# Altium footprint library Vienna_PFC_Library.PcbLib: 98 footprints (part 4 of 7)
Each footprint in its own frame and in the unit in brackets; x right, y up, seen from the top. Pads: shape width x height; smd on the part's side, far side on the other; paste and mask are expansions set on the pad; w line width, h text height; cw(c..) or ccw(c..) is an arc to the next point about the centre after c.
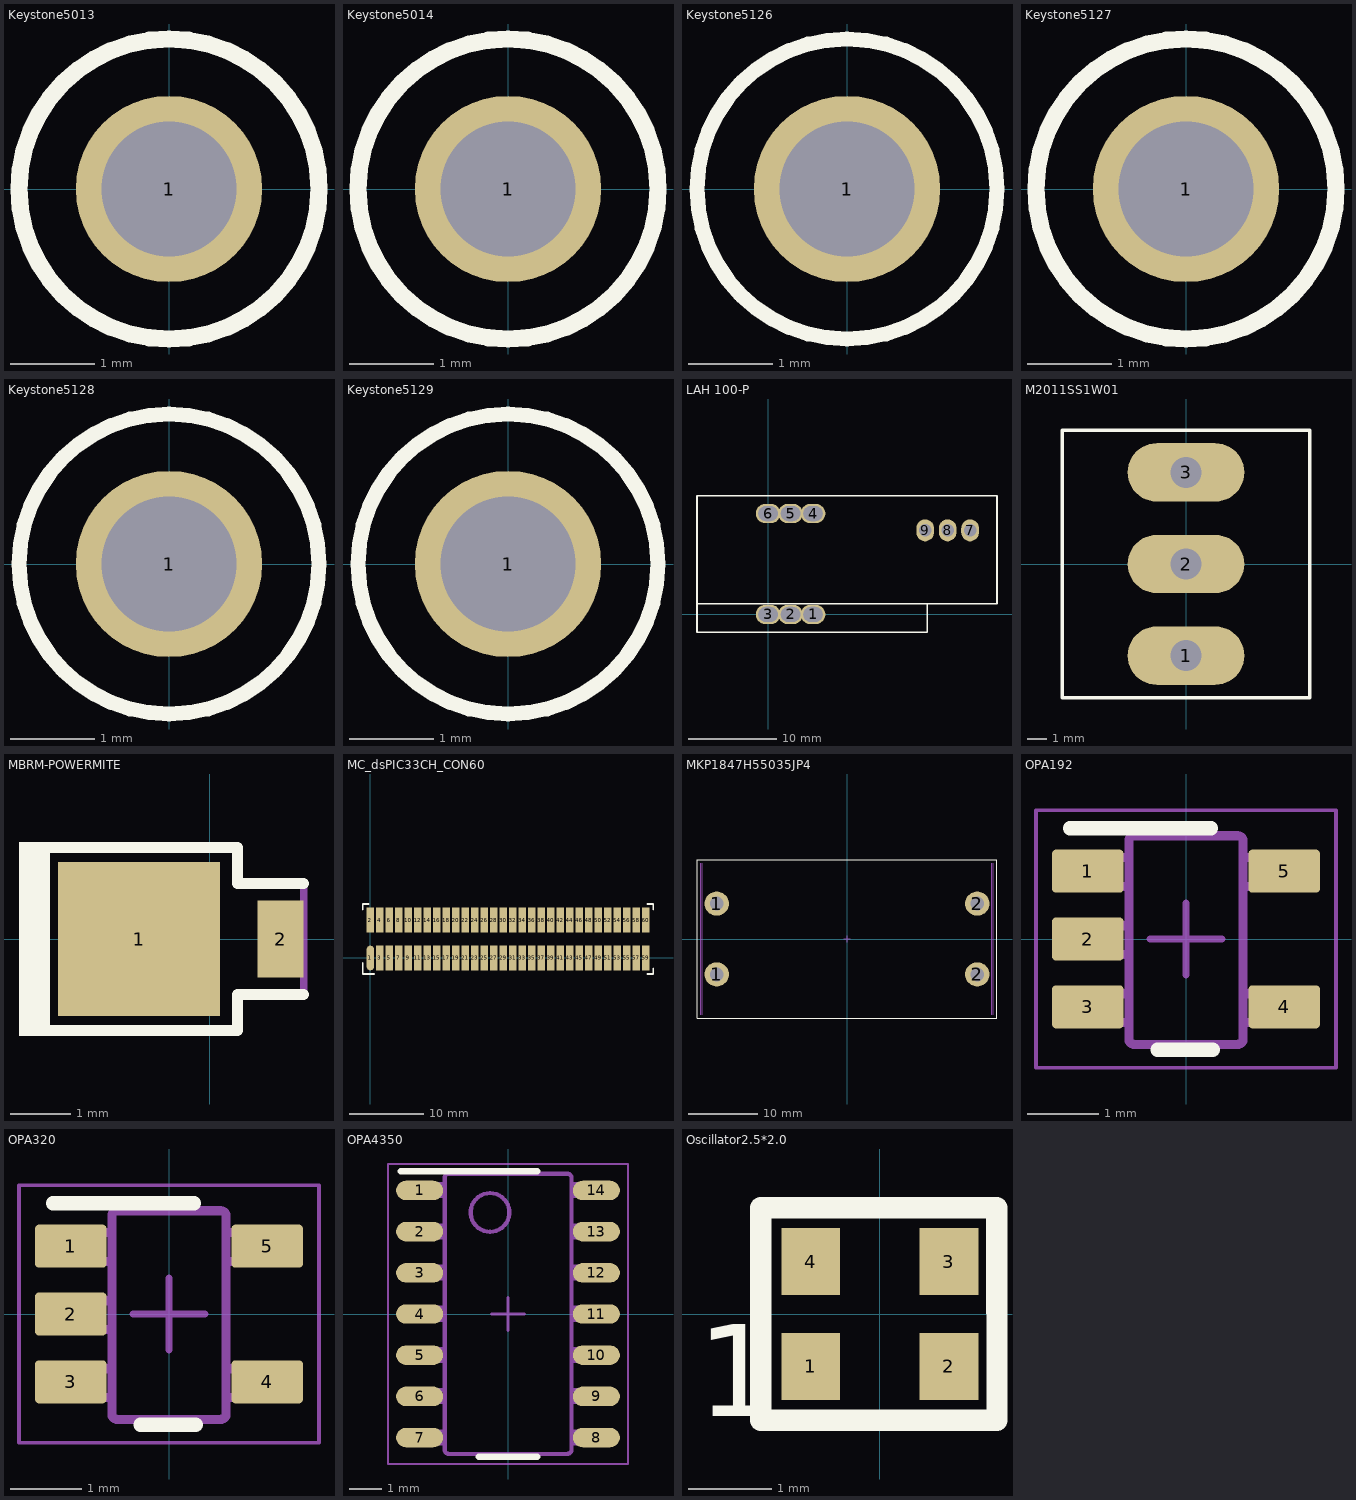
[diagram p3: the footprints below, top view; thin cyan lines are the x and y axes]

## Keystone5013 [mil] "Keystone Multipurpose loops"
height 320
pads (1):
  round 87 hole 63: 1(0,0)
Top Overlay:
  circle w7.99: c0,0 r70
Mechanical 5:
  circle w5: c0,0 r69.46
3D body "Keystone_5013.stp": height 318.9, standoff -125.98, extent -63,-63.5 62.74,62.49

## Keystone5014 [mil] "Keystone Multipurpose loops"
height 320
pads (1):
  round 87 hole 63: 1(0,0)
Top Overlay:
  circle w7.99: c0,0 r70
Mechanical 5:
  circle w5: c0,0 r69.46
3D body "Keystone_5014.stp": height 318.9, standoff -125.98, extent -63,-63.5 62.74,62.49

## Keystone5126 [mil] "Keystone Multipurpose loops"
height 320
pads (1):
  round 87 hole 63: 1(0,0)
Top Overlay:
  circle w7: c0,0 r70
Mechanical 5:
  circle w5: c0,0 r69.46
3D body "Keystone_5126.stp": height 318.9, standoff -125.98, extent -63.12,-63.37 62.86,62.36

## Keystone5127 [mil] "Keystone Multipurpose loops"
height 320
pads (1):
  round 87 hole 63: 1(0,0)
Top Overlay:
  circle w7.99: c0,0 r70
Mechanical 5:
  circle w5: c0,0 r69.46
3D body "Keystone_5127.stp": height 318.9, standoff -125.98, extent -63,-63.5 62.74,62.49

## Keystone5128 [mil] "Keystone Multipurpose loops"
height 320
pads (1):
  round 87 hole 63: 1(0,0)
Top Overlay:
  circle w7: c0,0 r70
Mechanical 5:
  circle w5: c0,0 r69.46
3D body "Keystone_5128.stp": height 318.9, standoff -125.98, extent -63.12,-63.37 62.86,62.36

## Keystone5129 [mil] "Keystone Multipurpose loops"
height 320
pads (1):
  round 87 hole 63: 1(0,0)
Top Overlay:
  circle w7: c0,0 r70
Mechanical 5:
  circle w5: c0,0 r69.46
3D body "Keystone_5129.stp": height 318.9, standoff -125.98, extent -63.12,-63.37 62.86,62.36

## LAH 100-P [mm] "Inductor"
height 24
pads (9):
  oval 2.8x2.2 hole 1.7 slot 2.2 at 0 deg: 1(5.08,0) 2(2.54,0) 3(0,0) 4(5.08,11.43) 5(2.54,11.43) 6(0,11.43)
  oval 2x2.5 hole 1.4: 7(22.86,9.525) 8(20.32,9.525) 9(17.78,9.525)
Top Overlay:
  lines w0.178: -7.964,1.23 25.908,1.23 ; 18.034,1.23 18.034,-2.032 -8.052,-2.032 -8.052,13.462 25.908,13.462 25.908,1.27
3D body "LAH 100-P_blackbox.stp": height 21.05, standoff -4.9, extent -7.76,-1.731 25.54,13.208

## M2011SS1W01 [mm] "Capacitor"
height 34
pads (3):
  oval 6x3 hole 1.6 square: 1(0,-4.7) 2(0,0) 3(0,4.7)
Top Overlay:
  lines w0.178: -6.35,-6.858 -6.35,6.858 6.35,6.858 6.35,-6.858 -6.35,-6.858
Mechanical 15:
  lines w0.1: -0.5,0 0.5,0 ; 0,-0.5 0,0.5
3D body "M2011SS1W01.stp": height 28.88, standoff -4.67, extent -6.019,-6.509 5.97,6.495

## MBRM-POWERMITE [mil] "On Semi recommended land pattern, 457-04.pdf Rev 04E dated 2008-11-26"
height 45.28
pads (2):
  rect 105x100 smd: 1(-46,0)
  rect 30x50 smd: 2(46,0)
Top Overlay:
  rectangle: -124,-63 -104,63
  lines w7: -109.7,-59.5 -19,-59.5 18,-59.5 18,-36 61,-36 ; -109.7,59.5 -19,59.5 18,59.5 18,36 61,36
Mechanical 5:
  rectangle: -124,-63 -104,63
  lines w5: -109.7,-59.5 -19,-59.5 18,-59.5 18,-36 61,-36 61,36 18,36 18,59.5 -19,59.5 -109.7,59.5
3D body "PowerMite.stp": height 45.31, standoff 0, extent -94.48,-40.35 59.06,40.36

## MC_Connector [mm] "Microchip dsPIC33CH Connector"

## MC_dsPIC33CH_CON60 [mil]
pads (60):
  oval 40x130 smd: 1(0,0)
  rect 40x130 smd: 2(0,200) 3(50,0) 4(50,200) 5(100,0) 6(100,200) 7(150,0) 8(150,200) 9(200,0) 10(200,200) 11(250,0) 12(250,200) 13(300,0) 14(300,200) 15(350,0) 16(350,200) 17(400,0) 18(400,200) 19(450,0) 20(450,200) 21(500,0) 22(500,200) 23(550,0) 24(550,200) 25(600,0) 26(600,200) 27(650,0) 28(650,200) 29(700,0) 30(700,200) 31(750,0) 32(750,200) 33(800,0) 34(800,200) 35(850,0) 36(850,200) 37(900,0) 38(900,200) 39(950,0) 40(950,200) 41(1000,0) 42(1000,200) 43(1050,0) 44(1050,200) 45(1100,0) 46(1100,200) 47(1150,0) 48(1150,200) 49(1200,0) 50(1200,200) 51(1250,0) 52(1250,200) 53(1300,0) 54(1300,200) 55(1350,0) 56(1350,200) 57(1400,0) 58(1400,200) 59(1450,0) 60(1450,200)
Top Overlay:
  lines w10: -40,-25 -40,-85 20,-85 ; -40,255 -40,285 -10,285 ; 1460,-85 1490,-85 1490,-55 ; 1460,285 1490,285 1490,255

## MKP1847H55035JP4 [mm] "Capacitor"
height 38.5
pads (4):
  round 3.5 hole 2: 1(-18.75,-5.1) 1(-18.75,5.1) 2(18.75,-5.1) 2(18.75,5.1)
Top Overlay:
  lines w0.178: -21.59,-11.43 -21.59,11.43 21.59,11.43 21.59,-11.43 -21.59,-11.43
Mechanical 13:
  lines w0.1: -21.082,-10.922 -21.082,10.922 ; -20.828,-10.922 -20.828,10.922 ; 20.828,-10.922 20.828,10.922 ; 21.082,-10.922 21.082,10.922
Mechanical 15:
  lines w0.1: -0.5,0 0.5,0 ; 0,-0.5 0,0.5
3D body: height 2.8, standoff 0, extent 20.794,-10.922 21.082,10.922
3D body: height 2.8, standoff 0, extent 20.828,-4.318 21.082,4.318
3D body: height 2.8, standoff 0, extent -21.082,-4.318 -20.828,4.318
3D body "MKP1847H55035+P4.step": height 39, standoff -6, extent -21.35,-11.1 21.35,11.1
3D body: height 2.8, standoff 0, extent -21.116,-10.922 -20.828,10.922

## OPA192 [mm] "SOT23, 5-Leads, Body 2.9x1.6mm, Pitch 0.95mm, Lead Span 2.8mm, IPC Medium Density"
height 1.45
pads (5):
  rrect17% 1x0.6 smd: 1(-1.375,0.95) 2(-1.375,0) 3(-1.375,-0.95) 4(1.375,-0.95) 5(1.375,0.95)
Top Overlay:
  lines w0.2: -1.625,1.55 0.35,1.55 ; -0.4,-1.55 0.375,-1.55
Mechanical 5:
  lines w0.127: -0.801,1.371 cw(c-0.725,1.37) -0.725,1.446 ; -0.801,1.37 -0.801,-1.399 -0.801,-1.4 ccw(c-0.725,-1.399) -0.725,-1.475 ; -0.801,1.37 -0.801,1.371 ; -0.725,-1.475 -0.725,-1.475 ; -0.725,-1.475 0.723,-1.475 0.724,-1.475 ccw(c0.723,-1.399) 0.799,-1.4 0.799,-1.399 0.799,1.37 ; -0.725,1.446 0.723,1.446 0.724,1.446 cw(c0.723,1.37) 0.799,1.371 ; -0.725,1.446 -0.725,1.446 ; 0.799,1.37 0.799,1.371 ; -1.423,-1.167 -1.199,-1.167 -1.105,-1.167 -1.088,-1.167 -0.835,-1.167 -0.801,-1.167 -0.801,-0.767 -0.835,-0.767 -1.088,-0.767 -1.105,-0.767 -1.199,-0.767 -1.423,-0.767 -1.423,-1.167 ; -1.423,-0.215 -1.199,-0.215 -1.105,-0.215 -1.088,-0.215 -0.835,-0.215 -0.801,-0.215 -0.801,0.186 -0.835,0.186 -1.088,0.186 -1.105,0.186 -1.199,0.186 -1.423,0.186 -1.423,-0.215 ; -1.423,0.738 -1.199,0.738 -1.105,0.738 -1.088,0.738 -0.835,0.738 -0.801,0.738 -0.801,1.138 -0.835,1.138 -1.088,1.138 -1.105,1.138 -1.199,1.138 -1.423,1.138 -1.423,0.738 ; 0.799,-1.167 0.799,-0.767 0.834,-0.767 1.087,-0.767 1.103,-0.767 1.198,-0.767 1.422,-0.767 1.422,-1.167 1.198,-1.167 1.103,-1.167 1.087,-1.167 0.834,-1.167 0.799,-1.167 ; 0.799,0.738 0.799,1.138 0.834,1.138 1.087,1.138 1.103,1.138 1.198,1.138 1.422,1.138 1.422,0.738 1.198,0.738 1.103,0.738 1.087,0.738 0.834,0.738 0.799,0.738
Mechanical 15:
  lines w0.05: -2.1,-1.8 2.1,-1.8 2.1,1.8 -2.1,1.8 -2.1,-1.8
  lines w0.1: -0.5,0 0.5,0 ; 0,-0.5 0,0.5
3D body "DBV0005A.stp": height 1.09, standoff 0, extent -1.422,-1.46 1.422,1.461

## OPA320 [mm] "SOT23, 5-Leads, Body 2.9x1.6mm, Pitch 0.95mm, Lead Span 2.8mm, IPC Medium Density"
height 1.45
pads (5):
  rrect17% 1x0.6 smd: 1(-1.375,0.95) 2(-1.375,0) 3(-1.375,-0.95) 4(1.375,-0.95) 5(1.375,0.95)
Top Overlay:
  lines w0.2: -1.625,1.55 0.35,1.55 ; -0.4,-1.55 0.375,-1.55
Mechanical 5:
  lines w0.127: -0.801,1.371 cw(c-0.725,1.37) -0.725,1.446 ; -0.801,1.37 -0.801,1.371 ; -0.801,1.37 -0.801,-1.399 -0.801,-1.4 ccw(c-0.725,-1.399) -0.725,-1.475 ; -0.725,-1.475 0.723,-1.475 0.724,-1.475 ccw(c0.723,-1.399) 0.799,-1.4 0.799,-1.399 0.799,1.37 ; -0.725,-1.475 -0.725,-1.475 ; -0.725,1.446 -0.725,1.446 ; -0.725,1.446 0.723,1.446 0.724,1.446 cw(c0.723,1.37) 0.799,1.371 ; 0.799,1.37 0.799,1.371 ; -1.423,-1.167 -1.423,-0.767 -1.199,-0.767 -1.105,-0.767 -1.088,-0.767 -0.835,-0.767 -0.801,-0.767 -0.801,-1.167 -0.835,-1.167 -1.088,-1.167 -1.105,-1.167 -1.199,-1.167 -1.423,-1.167 ; -1.423,-0.215 -1.423,0.186 -1.199,0.186 -1.105,0.186 -1.088,0.186 -0.835,0.186 -0.801,0.186 -0.801,-0.215 -0.835,-0.215 -1.088,-0.215 -1.105,-0.215 -1.199,-0.215 -1.423,-0.215 ; -1.423,0.738 -1.423,1.138 -1.199,1.138 -1.105,1.138 -1.088,1.138 -0.835,1.138 -0.801,1.138 -0.801,0.738 -0.835,0.738 -1.088,0.738 -1.105,0.738 -1.199,0.738 -1.423,0.738 ; 0.799,-1.167 0.834,-1.167 1.087,-1.167 1.103,-1.167 1.198,-1.167 1.422,-1.167 1.422,-0.767 1.198,-0.767 1.103,-0.767 1.087,-0.767 0.834,-0.767 0.799,-0.767 0.799,-1.167 ; 0.799,0.738 0.834,0.738 1.087,0.738 1.103,0.738 1.198,0.738 1.422,0.738 1.422,1.138 1.198,1.138 1.103,1.138 1.087,1.138 0.834,1.138 0.799,1.138 0.799,0.738
Mechanical 15:
  lines w0.05: -2.1,-1.8 -2.1,1.8 2.1,1.8 2.1,-1.8 -2.1,-1.8
  lines w0.1: -0.5,0 0.5,0 ; 0,-0.5 0,0.5
3D body "DBV0005A.stp": height 1.09, standoff 0, extent -1.422,-1.46 1.422,1.461

## OPA4350 [mm] "SOIC, 14-Leads, Body 8.7x3.9mm, Pitch 1.27mm, IPC Medium Density"
height 1.75
pads (14):
  oval 1.45x0.6 smd: 1(-2.725,3.81) 2(-2.725,2.54) 3(-2.725,1.27) 4(-2.725,0) 5(-2.725,-1.27) 6(-2.725,-2.54) 7(-2.725,-3.81) 8(2.725,-3.81) 9(2.725,-2.54) 10(2.725,-1.27) 11(2.725,0) 12(2.725,1.27) 13(2.725,2.54) 14(2.725,3.81)
Top Overlay:
  lines w0.2: -3.3,4.4 0.9,4.4 ; -0.9,-4.4 0.9,-4.4
Mechanical 5:
  drawing of 164 lines, arcs and shapes, not listed
Mechanical 15:
  lines w0.05: -3.7,-4.625 -3.7,4.625 3.7,4.625 3.7,-4.625 -3.7,-4.625
  lines w0.1: -0.5,0 0.5,0 ; 0,-0.5 0,0.5
3D body "D0014A.stp": height 1.6, standoff 0, extent -3.023,-4.318 3.023,4.318

## Oscillator2.5*2.0 [mm]
height 1.45
pads (4):
  rect 0.7x0.8 smd: 1(-0.825,-0.625) 2(0.825,-0.625) 3(0.825,0.625) 4(-0.825,0.625)
Top Overlay:
  lines w0.254: -1.422,-1.27 -1.422,1.27 1.395,1.27 1.399,-1.27 -1.422,-1.27
  text "1" at -2.184,-1.219 h1.1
